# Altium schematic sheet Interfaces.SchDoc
size A4; SheetNumber: 4; SheetTotal: 4
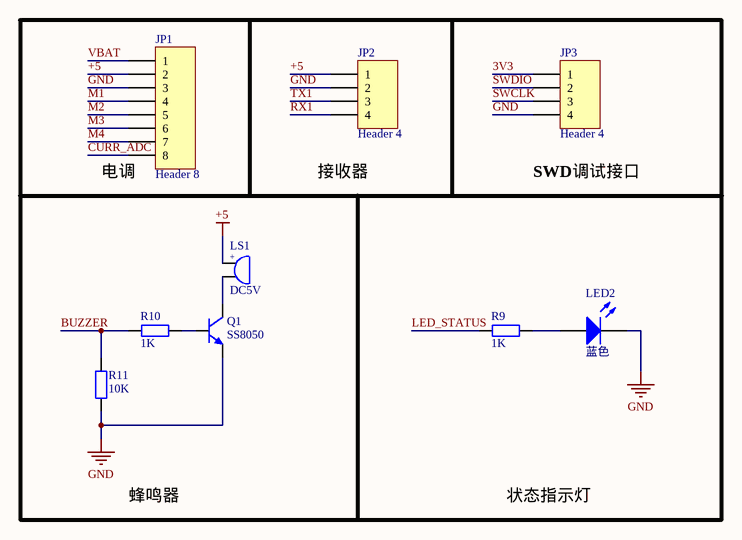
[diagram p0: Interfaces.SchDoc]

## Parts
JP1  Header 8  [SH1.0-WT-8P]
JP2  Header 4  [PAD-1X4-SMD]
JP3  Header 4  [PAD-1X4-SMD]
LED2  蓝色  [LED0603_B]
LS1  DC5V  [BUZZER]
Q1  SS8050  [SOT23-3L]
R9  1K  [R0402_M]
R10  1K  [R0402_M]
R11  10K  [R0402_M]

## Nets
+5: JP1.2 JP2.1 LS1.1
GND: JP1.3 JP2.2 JP3.4 LED2.2(K) Q1.2(E) R11.1
3V3: JP3.1
BUZZER: R10.1 R11.2
CURR_ADC: JP1.8
LED_STATUS: R9.1
M1: JP1.4
M2: JP1.5
M3: JP1.6
M4: JP1.7
RX1: JP2.4
SWCLK: JP3.3
SWDIO: JP3.2
TX1: JP2.3
VBAT: JP1.1
NetLED2_1: LED2.1(A) R9.2
NetLS1_2: LS1.2 Q1.3(C)
NetQ1_1: Q1.1(B) R10.2

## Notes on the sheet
- (near JP1) 电调
- (near JP2) 接收器
- (near JP3) SWD调试接口
- 蜂鸣器
- 状态指示灯

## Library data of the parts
JP1 = Header 8: Header, 8-Pin
JP2 JP3 = Header 4: Header, 4-Pin
LED2 = LED: 贴片LED; 封装库来自淘宝卖家：黄晶宝石: 其他店铺购入均为盗版封装库，无更新权益，请立即申请退款，本店现金奖励200~1000元
LS1 = BEEP: 蜂鸣器; 联系下单店铺卖家 免费技术支持: 联系下单店铺卖家 免费帮你查找封装
Q1 = 8050-SMD: 高频放大-NPN型; 参数: 40V 1.5A 1W 100MHZ; 联系下单店铺卖家 免费帮你查找封装: 联系下单店铺卖家 免费技术支持
R9-R11 = R: 贴片电阻; 联系下单店铺卖家 免费帮你查找封装: 联系下单店铺卖家 免费技术支持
